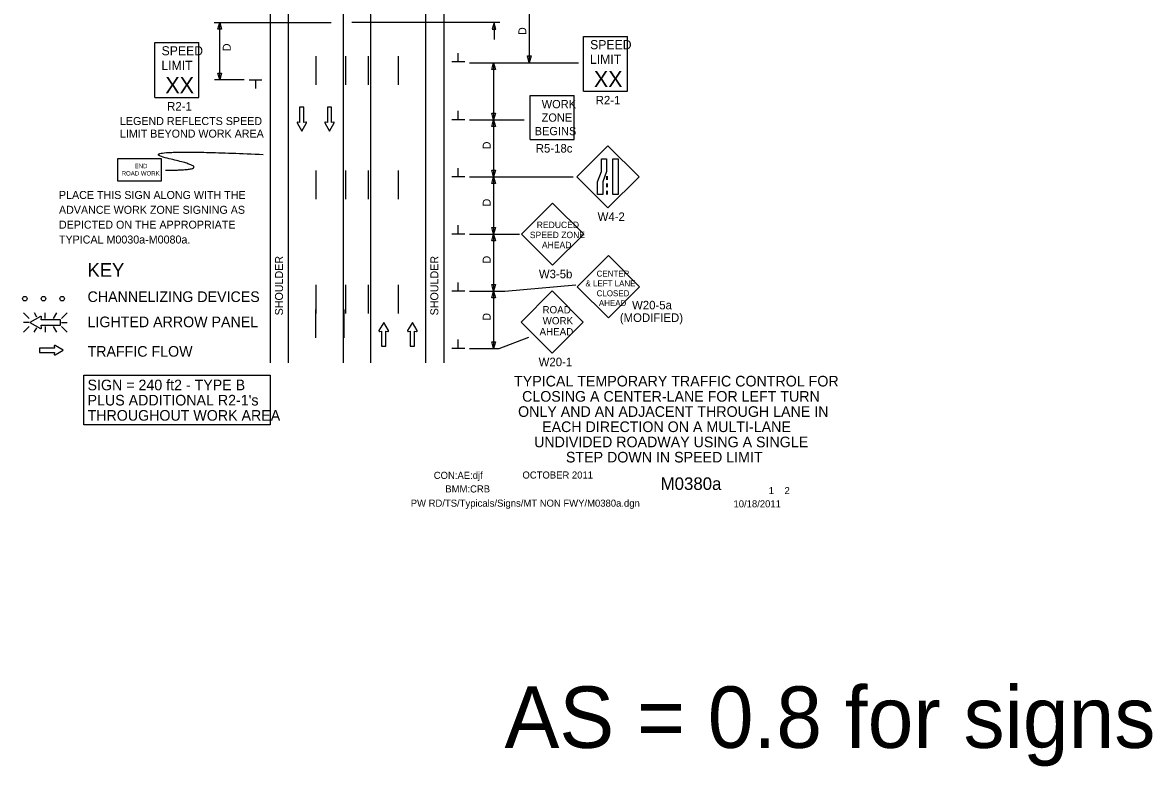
# Model space of a CAD drawing. Extents: x 16731 to 18475, y 5706 to 6928.
# Drawn here: x 16731 to 17719, y 5706 to 6357 of the extents above; entities that cross this region are included whole.
import ezdxf

# ---------------------------------------------------------------- set-up
doc = ezdxf.new("R2010")
doc.units = 0
for name, color, linetype in [('ALI_LEGAL_EX', 7, 'Continuous'), ('BORDER_SIGNAL_WO', 7, 'Continuous'), ('MT_SCRATCH_LEVEL_E', 7, 'Continuous'), ('PAVT_EDGE_EX', 7, 'Continuous'), ('TRAFFIC_SIGNS_PR', 7, 'Continuous'), ('TYPICAL_TEXT_DIMEN_EX', 7, 'Continuous'), ('TYPICAL_TEXT_DIMEN_PR', 7, 'Continuous')]:
    doc.layers.add(name, color=color, linetype=linetype)

msp = doc.modelspace()

# ---------------------------------------------------------------- linework, layer by layer
at = {"layer": 'ALI_LEGAL_EX'}
for points in [[(16987.43, 6327.88), (16987.43, 6302.88)], [(17013.43, 6327.88), (17013.43, 6302.88)], [(17033.43, 6327.88), (17033.43, 6302.88)], [(17059.43, 6327.88), (17059.43, 6302.88)], [(16987.43, 6227.88), (16987.43, 6202.88)], [(17013.43, 6227.88), (17013.43, 6202.88)], [(17033.43, 6227.88), (17033.43, 6202.88)], [(17059.43, 6227.88), (17059.43, 6202.88)], [(16987.43, 6127.88), (16987.43, 6102.88)], [(17013.43, 6127.88), (17013.43, 6102.88)], [(17033.43, 6127.88), (17033.43, 6102.88)], [(17059.43, 6127.88), (17059.43, 6102.88)]]:
    msp.add_lwpolyline(points, dxfattribs=at)
at = {"layer": 'MT_SCRATCH_LEVEL_E'}
for p, q in [((16977.1, 6283.22), (16973.36, 6283.22)), ((16973.36, 6283.22), (16973.36, 6269.96)), ((16977.1, 6283.22), (16973.36, 6283.22)), ((16973.36, 6283.22), (16973.36, 6269.96)), ((16977.1, 6269.96), (16977.1, 6283.22)), ((16977.1, 6269.96), (16977.1, 6283.22)), ((17001.36, 6283.22), (16997.62, 6283.22)), ((16997.62, 6283.22), (16997.62, 6269.96)), ((17001.36, 6283.22), (16997.62, 6283.22)), ((16997.62, 6283.22), (16997.62, 6269.96)), ((17001.36, 6269.96), (17001.36, 6283.22)), ((17001.36, 6269.96), (17001.36, 6283.22)), ((16971.1, 6269.59), (16975.25, 6262.35)), ((16971.1, 6269.59), (16975.25, 6262.35)), ((16973.36, 6269.96), (16971.58, 6270.28)), ((16973.36, 6269.96), (16971.58, 6270.28)), ((16975.25, 6262.35), (16979.36, 6269.59)), ((16975.25, 6262.35), (16979.36, 6269.59)), ((16978.88, 6270.28), (16977.1, 6269.96)), ((16978.88, 6270.28), (16977.1, 6269.96)), ((16995.36, 6269.59), (16999.51, 6262.35)), ((16995.36, 6269.59), (16999.51, 6262.35)), ((16997.62, 6269.96), (16995.84, 6270.28)), ((16997.62, 6269.96), (16995.84, 6270.28)), ((16999.51, 6262.35), (17003.62, 6269.59)), ((16999.51, 6262.35), (17003.62, 6269.59)), ((17003.14, 6270.28), (17001.36, 6269.96)), ((17003.14, 6270.28), (17001.36, 6269.96)), ((17046.87, 6095.01), (17042.76, 6087.77)), ((17046.87, 6095.01), (17042.76, 6087.77)), ((17051.02, 6087.77), (17046.87, 6095.01)), ((17051.02, 6087.77), (17046.87, 6095.01)), ((17071.96, 6095.01), (17067.85, 6087.77)), ((17071.96, 6095.01), (17067.85, 6087.77)), ((17076.11, 6087.77), (17071.96, 6095.01)), ((17076.11, 6087.77), (17071.96, 6095.01)), ((17043.24, 6087.09), (17045.02, 6087.4)), ((17043.24, 6087.09), (17045.02, 6087.4)), ((17045.02, 6087.4), (17045.02, 6074.14)), ((17045.02, 6087.4), (17045.02, 6074.14)), ((17048.76, 6074.14), (17048.76, 6087.4)), ((17048.76, 6087.4), (17050.54, 6087.09)), ((17048.76, 6074.14), (17048.76, 6087.4)), ((17048.76, 6087.4), (17050.54, 6087.09)), ((17068.33, 6087.09), (17070.11, 6087.4)), ((17068.33, 6087.09), (17070.11, 6087.4)), ((17070.11, 6087.4), (17070.11, 6074.14)), ((17070.11, 6087.4), (17070.11, 6074.14)), ((17073.85, 6074.14), (17073.85, 6087.4)), ((17073.85, 6087.4), (17075.63, 6087.09)), ((17073.85, 6074.14), (17073.85, 6087.4)), ((17073.85, 6087.4), (17075.63, 6087.09)), ((16758.97, 6072.47), (16745.71, 6072.47)), ((16745.71, 6072.47), (16745.71, 6068.72)), ((16758.97, 6072.47), (16745.71, 6072.47)), ((16745.71, 6072.47), (16745.71, 6068.72)), ((16758.66, 6074.24), (16758.97, 6072.47)), ((16758.66, 6074.24), (16758.97, 6072.47)), ((16766.58, 6070.61), (16759.34, 6074.72)), ((16766.58, 6070.61), (16759.34, 6074.72)), ((16759.34, 6066.47), (16766.58, 6070.61)), ((16759.34, 6066.47), (16766.58, 6070.61)), ((17045.02, 6074.14), (17048.76, 6074.14)), ((17045.02, 6074.14), (17048.76, 6074.14)), ((17070.11, 6074.14), (17073.85, 6074.14)), ((17070.11, 6074.14), (17073.85, 6074.14)), ((16745.71, 6068.72), (16758.97, 6068.72)), ((16745.71, 6068.72), (16758.97, 6068.72)), ((16758.97, 6068.72), (16758.66, 6066.95)), ((16758.97, 6068.72), (16758.66, 6066.95))]:
    msp.add_line(p, q, dxfattribs=at)
for centre, start, end in [((16971.51, 6269.82), 80.03619, 209.77312), ((16971.51, 6269.82), 80.03619, 209.77312), ((16978.96, 6269.82), 330.42484, 99.96381), ((16978.96, 6269.82), 330.42484, 99.96381), ((16995.77, 6269.82), 80.03619, 209.77312), ((16995.77, 6269.82), 80.03619, 209.77312), ((17003.21, 6269.82), 330.42484, 99.96381), ((17003.21, 6269.82), 330.42484, 99.96381), ((17043.17, 6087.55), 150.42484, 279.96381), ((17043.17, 6087.55), 150.42484, 279.96381), ((17050.61, 6087.55), 260.03619, 29.77312), ((17050.61, 6087.55), 260.03619, 29.77312), ((17068.26, 6087.55), 150.42484, 279.96381), ((17068.26, 6087.55), 150.42484, 279.96381), ((17075.7, 6087.55), 260.03619, 29.77312), ((17075.7, 6087.55), 260.03619, 29.77312), ((16759.11, 6074.32), 60.42484, 189.96381), ((16759.11, 6074.32), 60.42484, 189.96381), ((16759.12, 6066.88), 170.03619, 299.77312), ((16759.12, 6066.88), 170.03619, 299.77312)]:
    msp.add_arc(centre, 0.463, start, end, dxfattribs=at)
at = {"layer": 'PAVT_EDGE_EX'}
for p, q in [((16947.43, 6926.45), (16947.43, 6059.71)), ((16963.43, 6926.45), (16963.43, 6059.71)), ((17011.43, 6926.45), (17011.43, 6059.71)), ((17035.43, 6926.45), (17035.43, 6059.71)), ((17083.43, 6926.45), (17083.43, 6059.71)), ((17099.43, 6926.45), (17099.43, 6059.71))]:
    msp.add_line(p, q, dxfattribs=at)
for points in [[(16987.43, 6081.34), (16987.43, 6106.34)], [(17012.43, 6081.34), (17012.43, 6106.34)]]:
    msp.add_lwpolyline(points, dxfattribs=at)
at = {"layer": 'TRAFFIC_SIGNS_PR'}
for p, q in [((16846.77, 6339.81), (16885.17, 6339.81)), ((16846.77, 6291.81), (16846.77, 6339.81)), ((16885.17, 6291.81), (16885.17, 6339.81)), ((17221.71, 6345.18), (17260.11, 6345.18)), ((17221.71, 6297.18), (17221.71, 6345.18)), ((17260.11, 6297.18), (17260.11, 6345.18)), ((17221.71, 6297.18), (17260.11, 6297.18)), ((16846.77, 6291.81), (16885.17, 6291.81)), ((17175.17, 6255.03), (17175.17, 6293.43)), ((17175.17, 6293.43), (17213.57, 6293.43)), ((17213.57, 6255.03), (17213.57, 6293.43)), ((17175.17, 6255.03), (17213.57, 6255.03)), ((17243.13, 6249.5), (17215.97, 6222.34)), ((17270.28, 6222.34), (17243.13, 6249.5)), ((17215.97, 6222.34), (17243.13, 6195.19)), ((17241.88, 6222.83), (17241.88, 6219.63)), ((17242.28, 6222.83), (17242.28, 6219.63)), ((17243.13, 6195.19), (17270.28, 6222.34)), ((17241.88, 6216.43), (17241.88, 6213.23)), ((17241.88, 6210.03), (17241.88, 6206.83)), ((17242.28, 6216.43), (17242.28, 6213.23)), ((17242.28, 6210.03), (17242.28, 6206.83)), ((17194.73, 6199.36), (17167.58, 6172.21)), ((17221.88, 6172.21), (17194.73, 6199.36)), ((17167.58, 6172.21), (17194.73, 6145.06)), ((17194.73, 6145.06), (17221.88, 6172.21)), ((17243.44, 6153.41), (17216.25, 6126.22)), ((17270.63, 6126.22), (17243.44, 6153.41)), ((17194.3, 6122.5), (17167.12, 6095.31)), ((17221.49, 6095.31), (17194.3, 6122.5)), ((17216.25, 6126.22), (17243.44, 6099.04)), ((17243.44, 6099.04), (17270.63, 6126.22)), ((16731.69, 6103.43), (16736.63, 6098.5)), ((16743.45, 6099.61), (16741.25, 6103.43)), ((16750.77, 6098.5), (16750.77, 6103.43)), ((16758.01, 6098.5), (16760.86, 6103.43)), ((16764.92, 6098.5), (16769.86, 6103.43)), ((16736.63, 6094.94), (16731.69, 6094.94)), ((16731.69, 6086.45), (16736.63, 6091.39)), ((16741.2, 6086.45), (16743.32, 6090.11)), ((16750.77, 6091.39), (16750.77, 6086.45)), ((16760.9, 6086.45), (16758.05, 6091.39)), ((16764.92, 6094.94), (16769.86, 6094.94)), ((16764.92, 6091.39), (16769.86, 6086.45)), ((17167.12, 6095.31), (17194.3, 6068.13)), ((17194.3, 6068.13), (17221.49, 6095.31))]:
    msp.add_line(p, q, dxfattribs=at)
for points in [[(16814.04, 6218.78), (16852.44, 6218.78), (16852.44, 6237.98), (16814.04, 6237.98)], [(17241.88, 6238.08), (17241.88, 6226.9), (17238.53, 6218.02), (17238.53, 6206.83), (17234.04, 6206.83), (17234.04, 6218.02), (17237.39, 6226.9), (17237.39, 6238.08)], [(17252.01, 6238.08), (17252.01, 6206.83), (17247.52, 6206.83), (17247.52, 6238.08)]]:
    msp.add_lwpolyline(points, close=True, dxfattribs=at)
for points in [[(16746.7, 6100.22), (16737.41, 6094.94), (16746.7, 6089.62)], [(16747.58, 6090.25), (16747.18, 6092.52), (16764.19, 6092.52), (16764.19, 6097.32), (16747.18, 6097.32), (16747.58, 6099.6)]]:
    msp.add_lwpolyline(points, dxfattribs=at)
for centre in [(16732.95, 6115.77), (16749.25, 6115.77), (16765.55, 6115.77)]:
    msp.add_circle(centre, 2, dxfattribs=at)
for centre, radius, start, end in [((16746.99, 6099.69), 0.598, 350.73078, 118.89165), ((16746.99, 6090.14), 0.597, 241.48329, 9.95933)]:
    msp.add_arc(centre, radius, start, end, dxfattribs=at)
msp.add_open_spline([(16856.03, 6228.16), (16903.27, 6228.16), (16818.24, 6247.5), (16941.34, 6242.01)], degree=2, dxfattribs=at)
at = {"layer": 'TYPICAL_TEXT_DIMEN_EX'}
msp.add_lwpolyline([(16784.45, 6048.7), (16947.63, 6048.7), (16947.63, 6005.33), (16784.45, 6005.33)], close=True, dxfattribs=at)
at = {"layer": 'TYPICAL_TEXT_DIMEN_PR'}
for p, q in [((17174.28, 6372.25), (17174.28, 6322.25)), ((16898.43, 6357.33), (17000.85, 6357.33)), ((16901.86, 6351.47), (16903.43, 6357.33)), ((16903.43, 6307.33), (16903.43, 6357.33)), ((16903.43, 6357.33), (16905, 6351.47)), ((17148.43, 6357.33), (17019.11, 6357.33)), ((17143.43, 6357.33), (17141.86, 6351.47)), ((17143.43, 6357.33), (17143.43, 6342.41)), ((17145, 6351.47), (17143.43, 6357.33)), ((16903.43, 6351.47), (16901.86, 6351.47)), ((16905, 6351.47), (16903.43, 6351.47)), ((17141.86, 6351.47), (17143.43, 6351.47)), ((17143.43, 6351.47), (17145, 6351.47)), ((17112.19, 6322.9), (17112.19, 6330.69)), ((17174.28, 6322.25), (17172.71, 6328.11)), ((17172.71, 6328.11), (17174.28, 6328.11)), ((17174.28, 6328.11), (17175.85, 6328.11)), ((17175.85, 6328.11), (17174.28, 6322.25)), ((17117.82, 6322.9), (17106.57, 6322.9)), ((17122.07, 6322.25), (17217.44, 6322.25)), ((17141.5, 6316.39), (17143.07, 6322.25)), ((17143.07, 6322.25), (17143.07, 6272.25)), ((17143.07, 6322.25), (17144.64, 6316.39)), ((16924.8, 6307.33), (16898.8, 6307.33)), ((16903.43, 6307.33), (16901.86, 6313.19)), ((16901.86, 6313.19), (16903.43, 6313.19)), ((16903.43, 6313.19), (16905, 6313.19)), ((16905, 6313.19), (16903.43, 6307.33)), ((16929.05, 6307.33), (16940.3, 6307.33)), ((16934.68, 6307.33), (16934.68, 6299.54)), ((17143.07, 6316.39), (17141.5, 6316.39)), ((17144.64, 6316.39), (17143.07, 6316.39)), ((17112.19, 6272.25), (17112.19, 6280.03)), ((17143.07, 6272.25), (17141.5, 6278.11)), ((17141.5, 6278.11), (17143.07, 6278.11)), ((17143.07, 6278.11), (17144.64, 6278.11)), ((17144.64, 6278.11), (17143.07, 6272.25)), ((17117.82, 6272.25), (17106.57, 6272.25)), ((17122.07, 6272.25), (17169.94, 6272.25)), ((17141.5, 6266.39), (17143.07, 6272.25)), ((17143.07, 6272.25), (17143.07, 6222.25)), ((17143.07, 6272.25), (17144.64, 6266.39)), ((17143.07, 6266.39), (17141.5, 6266.39)), ((17144.64, 6266.39), (17143.07, 6266.39)), ((17112.19, 6222.25), (17112.19, 6230.03)), ((17143.07, 6222.25), (17141.5, 6228.11)), ((17141.5, 6228.11), (17143.07, 6228.11)), ((17143.07, 6222.25), (17141.5, 6228.11)), ((17141.5, 6228.11), (17143.07, 6228.11)), ((17143.07, 6228.11), (17144.64, 6228.11)), ((17144.64, 6228.11), (17143.07, 6222.25)), ((17143.07, 6228.11), (17144.64, 6228.11)), ((17144.64, 6228.11), (17143.07, 6222.25)), ((17117.82, 6222.25), (17106.57, 6222.25)), ((17122.07, 6222.25), (17212.78, 6222.25)), ((17141.5, 6216.39), (17143.07, 6222.25)), ((17143.07, 6222.25), (17143.07, 6172.25)), ((17143.07, 6222.25), (17144.64, 6216.39)), ((17143.07, 6216.39), (17141.5, 6216.39)), ((17144.64, 6216.39), (17143.07, 6216.39)), ((17112.19, 6172.25), (17112.19, 6180.03)), ((17117.82, 6172.25), (17106.57, 6172.25)), ((17122.07, 6172.25), (17165.81, 6172.25)), ((17143.07, 6172.25), (17141.5, 6178.11)), ((17141.5, 6178.11), (17143.07, 6178.11)), ((17141.5, 6166.39), (17143.07, 6172.25)), ((17143.07, 6178.11), (17144.64, 6178.11)), ((17144.64, 6178.11), (17143.07, 6172.25)), ((17143.07, 6172.25), (17143.07, 6122.25)), ((17143.07, 6172.25), (17144.64, 6166.39)), ((17143.07, 6166.39), (17141.5, 6166.39)), ((17144.64, 6166.39), (17143.07, 6166.39)), ((17112.19, 6122.25), (17112.19, 6130.03)), ((17117.82, 6122.25), (17106.57, 6122.25)), ((17122.07, 6122.25), (17152.81, 6122.25)), ((17143.07, 6122.25), (17141.5, 6128.11)), ((17141.5, 6128.11), (17143.07, 6128.11)), ((17141.5, 6116.39), (17143.07, 6122.25)), ((17143.07, 6128.11), (17144.64, 6128.11)), ((17144.64, 6128.11), (17143.07, 6122.25)), ((17143.07, 6122.25), (17143.07, 6072.25)), ((17143.07, 6122.25), (17144.64, 6116.39)), ((17152.81, 6122.25), (17214.92, 6127.82)), ((17143.07, 6116.39), (17141.5, 6116.39)), ((17144.64, 6116.39), (17143.07, 6116.39)), ((17112.19, 6072.25), (17112.19, 6080.03)), ((17148.07, 6072.25), (17173.87, 6081.96)), ((17117.82, 6072.25), (17106.57, 6072.25)), ((17122.07, 6072.25), (17148.07, 6072.25)), ((17143.07, 6072.25), (17141.5, 6078.11)), ((17141.5, 6078.11), (17143.07, 6078.11)), ((17143.07, 6078.11), (17144.64, 6078.11)), ((17144.64, 6078.11), (17143.07, 6072.25))]:
    msp.add_line(p, q, dxfattribs=at)

# ---------------------------------------------------------------- texts
at = {"layer": 'BORDER_SIGNAL_WO'}
for s, height, p in [('TYPICAL TEMPORARY TRAFFIC CONTROL FOR', 9.3, (17160.98, 6038.92)), ('CLOSING A CENTER-LANE FOR LEFT TURN', 9.3, (17167.98, 6025.62)), ('ONLY AND AN ADJACENT THROUGH LANE IN', 9.3, (17164.48, 6012.32)), ('EACH DIRECTION ON A MULTI-LANE', 9.3, (17185.5, 5999.02)), ('UNDIVIDED ROADWAY USING A SINGLE', 9.3, (17178.5, 5985.72)), ('STEP DOWN IN SPEED LIMIT', 9.3, (17206.35, 5972.42)), ('CON:AE:djf', 6.2, (17090.69, 5958.06)), ('    OCTOBER 2011    ', 6.2, (17159.08, 5958.34)), ('BMM:CRB   ', 6.2, (17100.81, 5946.17)), ('    M0380a   ', 11, (17272.86, 5948.38)), (' 1    2 ', 6.2, (17381.45, 5944.7)), ('PW RD/TS/Typicals/Signs/MT NON FWY/M0380a.dgn    ', 6.2, (17070.55, 5933.71)), ('10/18/2011    ', 6.2, (17352.93, 5933.13))]:
    msp.add_text(s, height=height, dxfattribs=at).set_placement(p)
at = {"layer": 'TRAFFIC_SIGNS_PR'}
for s, height, p in [('SPEED', 8, (16852.54, 6328.67)), ('SPEED', 8, (17227.48, 6334.04)), ('LIMIT', 8, (17227.32, 6321.24)), ('LIMIT', 8, (16852.37, 6315.87)), ('XX', 14.031, (16855.88, 6295.57)), ('XX', 14.031, (17230.82, 6300.93)), ('R2-1', 7.44, (16857.45, 6280.37)), ('WORK', 7.217, (17185.16, 6282.39)), ('R2-1', 7.44, (17232.39, 6285.74)), ('ZONE', 7.217, (17185.05, 6270.58)), ('LEGEND REFLECTS SPEED', 7, (16816.13, 6267.68)), ('LIMIT BEYOND WORK AREA', 7, (16816.13, 6256.68)), ('BEGINS', 7.217, (17178.97, 6258.78)), ('R5-18c', 7.44, (17179.98, 6243.59)), ('END', 3.831, (16829.04, 6229.91)), ('ROAD WORK', 3.831, (16817.65, 6223.52)), ('PLACE THIS SIGN ALONG WITH THE', 7, (16762.76, 6203)), ('ADVANCE WORK ZONE SIGNING AS', 7, (16762.76, 6190)), ('W4-2', 7.44, (17234.08, 6183.75)), ('DEPICTED ON THE APPROPRIATE', 7, (16762.76, 6177)), ('REDUCED', 5.6, (17180.79, 6177.52)), ('TYPICAL M0030a-M0080a.', 7, (16762.76, 6164)), ('SPEED ZONE', 5.6, (17174.78, 6168.72)), ('AHEAD', 5.6, (17185.34, 6159.92)), ('W3-5b', 7.44, (17182.68, 6133.62)), ('CENTER', 5.206, (17233.21, 6135.08)), ('& LEFT LANE', 5.2065, (17223.46, 6126.47)), ('CLOSED', 5.206, (17233.21, 6117.86)), ('ROAD', 6.408, (17185.83, 6102.86)), ('AHEAD', 5.206, (17235.16, 6109.25)), ('W20-5a', 7.449, (17264.2, 6106.4)), ('WORK', 6.408, (17185.94, 6093.25)), ('(MODIFIED)', 7.449, (17253.48, 6095.39)), ('AHEAD', 6.408, (17183.25, 6083.64)), ('W20-1', 7.449, (17182.46, 6056.67))]:
    msp.add_text(s, height=height, dxfattribs=at).set_placement(p)
at = {"layer": 'TYPICAL_TEXT_DIMEN_EX'}
for s, height, p in [('KEY', 12, (16787.79, 6134.88)), ('CHANNELIZING DEVICES', 9.3, (16787.79, 6112.83)), ('LIGHTED ARROW PANEL', 9.3, (16787.79, 6090.78)), ('TRAFFIC FLOW', 9.3, (16787.79, 6064.98)), ('SIGN = 240 ft2 - TYPE B', 9.3, (16787.79, 6035.58)), ("PLUS ADDITIONAL R2-1's", 9.3, (16787.79, 6022.28)), ('THROUGHOUT WORK AREA', 9.3, (16787.79, 6008.98))]:
    msp.add_text(s, height=height, dxfattribs=at).set_placement(p)
at = {"layer": 'TYPICAL_TEXT_DIMEN_PR'}
for s, p in [('D', (17171.72, 6346.47)), ('D', (16913.07, 6332.26)), ('D', (17140.51, 6246.47)), ('D', (17140.51, 6246.47)), ('D', (17140.51, 6196.47)), ('SHOULDER', (16958.81, 6101.12)), ('SHOULDER', (17094.71, 6101.12)), ('D', (17140.51, 6146.47)), ('D', (17140.51, 6096.47))]:
    msp.add_text(s, height=7, rotation=90, dxfattribs=at).set_placement(p)
msp.add_text('AS = 0.8 for signs', height=53.76, dxfattribs=at).set_placement((17152.63, 5722.68))

doc.saveas('drawing.dxf')
